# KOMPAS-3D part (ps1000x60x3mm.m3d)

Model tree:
1. XY Plane
2. ZX Plane
3. ZY Plane
4. X Axis
5. Y Axis
6. Z Axis
7. Origin
8. Operation without History:1  (labels: nVent ERIFLEX / PS1000X60X3MM; PS1000X60X3MM)

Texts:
  nVent ERIFLEX / PS1000X60X3MM
  PS Protection Screen, Side Mount, 2.362" x 39.37"
  PS1000X60X3MM
  https://www.nvent.com/eriflex/products/efsPS1000X60X3MM
  PS Protection Screen
  90-24062020-026206OU7AK6CQSJ0RVYTMWTI79959
  Plane through Three Vertices
  Plane at Angle
  Plane through Edge and Vertex
  Axis through Two Vertices
  Conical Surface Axis
  Axis through Edge
  Operation without History
  Array by Grid
  Axis on Intersection of Two Planes
  Plane through Two Edges
  Plane through Edge and Face
  Array by Concentric Grid
  Array along Curve
  Surface without history
  Surface of extrusion
  Surface of revolution
  Surface of cross-sections
  Bend in Line
  Hole in Sheet Body
  Cut in Sheet Body
  Point in CG
  Linear from Segment to Point
  Geometric Tolerance Symbol
  Bend by Sketch
  Junction of Curves
  Array by points
  Surface by point grid
  Point Group by Curve
  Surface by curve grid
  Point Group from File
  Curve Equidistant Line
  Surface by point stratum
  Axis through Vertex along Object
  Curve without History
  Plane Tangent at Point
  Plane through Plane Curve
  Point Group by Surface
  Distance and angle
  Array by table
  Curve by 2 projections
  Curve by law
  Isoparametric curve group
  Surface of connection
  Linear dimension of the operation
  Angular dimension of the operation
  Radial dimension of the operation
  Diameter dimension of the operation
  Linear dimension of the sketch
  Angular dimension of the sketch
  Angular dimension of the broken sketch
  Radial dimension of the sketch
  Radial dimension of the bent sketch
  Diameter dimension of the sketch
  Array by Sample
  Operation from library
  Linear dimension without history
  Angular dimension without history
  Radial dimension without history
  Diameter dimension without history
  Unspecified Surface Finish
  Linear dimension of the broken line
  Text on drawing
  Leader #1
  Leader #2
  Leader #3
  Shape Deviations and Datum
  Node point number
  Mark of coordination axis
  Node point designation
  Mark/reference number with leader
  Mark/reference number on line
  Mark/reference number without leader
  Report Table Header
  Report Table Cell
  Report table name
  Component from Library
  Macroelement 2D
  Surface finish not set
  Processing method not specified
  Delete material layer
  Without Material Removal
